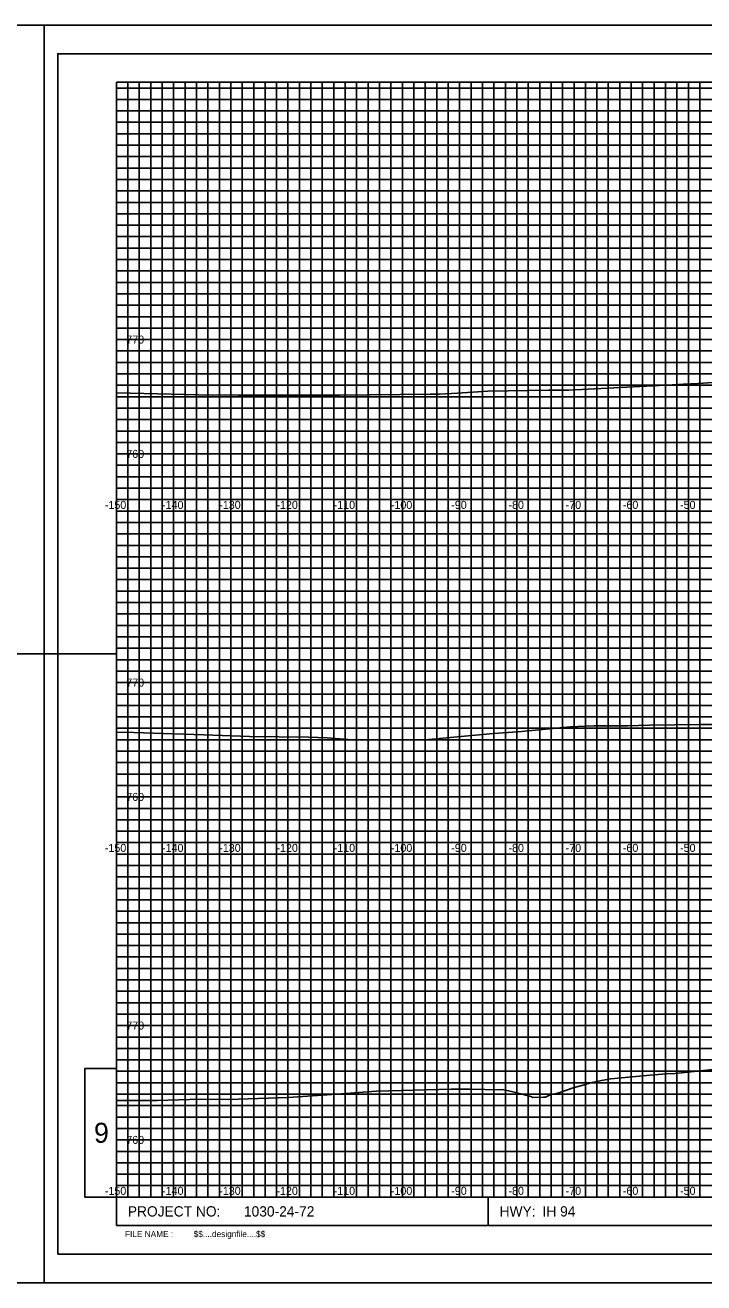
# Model space of a CAD drawing. Extents: x 578243 to 601557, y 174899 to 175559.
# Drawn here: x 601213.9 to 601332.5, y 175338.8 to 175558.8 of the extents above; entities that cross this region are included whole.
import ezdxf

# ---------------------------------------------------------------- set-up
doc = ezdxf.new("R2010")
doc.units = 0
for name, color, linetype in [('E_PROF_Grid', 7, 'Continuous'), ('E_PROF_GridMin', 7, 'Continuous'), ('P_E_XS_Ground', 7, 'Continuous'), ('P_XS_Text', 7, 'Continuous'), ('PLT_Sheet_Border', 7, 'Continuous'), ('PLT_Sheet_Info', 7, 'Continuous')]:
    doc.layers.add(name, color=color, linetype=linetype)

msp = doc.modelspace()

# ---------------------------------------------------------------- linework, layer by layer
at = {"layer": 'E_PROF_Grid'}
for p, q in [((601239.84, 175353.8), (601239.84, 175548.8)), ((601249.84, 175353.8), (601249.84, 175548.8)), ((601259.84, 175353.8), (601259.84, 175548.8)), ((601269.84, 175353.8), (601269.84, 175548.8)), ((601279.84, 175353.8), (601279.84, 175548.8)), ((601289.84, 175353.8), (601289.84, 175548.8)), ((601299.84, 175353.8), (601299.84, 175548.8)), ((601309.84, 175353.8), (601309.84, 175548.8)), ((601319.84, 175353.8), (601319.84, 175548.8)), ((601329.84, 175353.8), (601329.84, 175548.8)), ((601229.84, 175543.8), (601544.84, 175543.8)), ((601229.84, 175533.8), (601544.84, 175533.8)), ((601229.84, 175523.8), (601544.84, 175523.8)), ((601229.84, 175513.8), (601544.84, 175513.8)), ((601229.84, 175503.8), (601544.84, 175503.8)), ((601229.84, 175493.8), (601544.84, 175493.8)), ((601229.84, 175483.8), (601544.84, 175483.8)), ((601229.84, 175473.8), (601544.84, 175473.8)), ((601229.84, 175463.8), (601544.84, 175463.8)), ((601229.84, 175453.8), (601544.84, 175453.8)), ((601229.84, 175443.8), (601544.84, 175443.8)), ((601229.84, 175433.8), (601544.84, 175433.8)), ((601229.84, 175423.8), (601544.84, 175423.8)), ((601229.84, 175413.8), (601544.84, 175413.8)), ((601229.84, 175403.8), (601544.84, 175403.8)), ((601229.84, 175393.8), (601544.84, 175393.8)), ((601229.84, 175383.8), (601544.84, 175383.8)), ((601229.84, 175373.8), (601544.84, 175373.8)), ((601229.84, 175363.8), (601544.84, 175363.8))]:
    msp.add_line(p, q, dxfattribs=at)
at = {"layer": 'E_PROF_GridMin'}
for p, q in [((601229.84, 175547.8), (601544.84, 175547.8)), ((601231.84, 175353.8), (601231.84, 175548.8)), ((601233.84, 175353.8), (601233.84, 175548.8)), ((601235.84, 175353.8), (601235.84, 175548.8)), ((601237.84, 175353.8), (601237.84, 175548.8)), ((601241.84, 175353.8), (601241.84, 175548.8)), ((601243.84, 175353.8), (601243.84, 175548.8)), ((601245.84, 175353.8), (601245.84, 175548.8)), ((601247.84, 175353.8), (601247.84, 175548.8)), ((601251.84, 175353.8), (601251.84, 175548.8)), ((601253.84, 175353.8), (601253.84, 175548.8)), ((601255.84, 175353.8), (601255.84, 175548.8)), ((601257.84, 175353.8), (601257.84, 175548.8)), ((601261.84, 175353.8), (601261.84, 175548.8)), ((601263.84, 175353.8), (601263.84, 175548.8)), ((601265.84, 175353.8), (601265.84, 175548.8)), ((601267.84, 175353.8), (601267.84, 175548.8)), ((601271.84, 175353.8), (601271.84, 175548.8)), ((601273.84, 175353.8), (601273.84, 175548.8)), ((601275.84, 175353.8), (601275.84, 175548.8)), ((601277.84, 175353.8), (601277.84, 175548.8)), ((601281.84, 175353.8), (601281.84, 175548.8)), ((601283.84, 175353.8), (601283.84, 175548.8)), ((601285.84, 175353.8), (601285.84, 175548.8)), ((601287.84, 175353.8), (601287.84, 175548.8)), ((601291.84, 175353.8), (601291.84, 175548.8)), ((601293.84, 175353.8), (601293.84, 175548.8)), ((601295.84, 175353.8), (601295.84, 175548.8)), ((601297.84, 175353.8), (601297.84, 175548.8)), ((601301.84, 175353.8), (601301.84, 175548.8)), ((601303.84, 175353.8), (601303.84, 175548.8)), ((601305.84, 175353.8), (601305.84, 175548.8)), ((601307.84, 175353.8), (601307.84, 175548.8)), ((601311.84, 175353.8), (601311.84, 175548.8)), ((601313.84, 175353.8), (601313.84, 175548.8)), ((601315.84, 175353.8), (601315.84, 175548.8)), ((601317.84, 175353.8), (601317.84, 175548.8)), ((601321.84, 175353.8), (601321.84, 175548.8)), ((601323.84, 175353.8), (601323.84, 175548.8)), ((601325.84, 175353.8), (601325.84, 175548.8)), ((601327.84, 175353.8), (601327.84, 175548.8)), ((601331.84, 175353.8), (601331.84, 175548.8)), ((601229.84, 175545.8), (601544.84, 175545.8)), ((601229.84, 175541.8), (601544.84, 175541.8)), ((601229.84, 175539.8), (601544.84, 175539.8)), ((601229.84, 175537.8), (601544.84, 175537.8)), ((601229.84, 175535.8), (601544.84, 175535.8)), ((601229.84, 175531.8), (601544.84, 175531.8)), ((601229.84, 175529.8), (601544.84, 175529.8)), ((601229.84, 175527.8), (601544.84, 175527.8)), ((601229.84, 175525.8), (601544.84, 175525.8)), ((601229.84, 175521.8), (601544.84, 175521.8)), ((601229.84, 175519.8), (601544.84, 175519.8)), ((601229.84, 175517.8), (601544.84, 175517.8)), ((601229.84, 175515.8), (601544.84, 175515.8)), ((601229.84, 175511.8), (601544.84, 175511.8)), ((601229.84, 175509.8), (601544.84, 175509.8)), ((601229.84, 175507.8), (601544.84, 175507.8)), ((601229.84, 175505.8), (601544.84, 175505.8)), ((601229.84, 175501.8), (601544.84, 175501.8)), ((601229.84, 175499.8), (601544.84, 175499.8)), ((601229.84, 175497.8), (601544.84, 175497.8)), ((601229.84, 175495.8), (601544.84, 175495.8)), ((601229.84, 175491.8), (601544.84, 175491.8)), ((601229.84, 175489.8), (601544.84, 175489.8)), ((601229.84, 175487.8), (601544.84, 175487.8)), ((601229.84, 175485.8), (601544.84, 175485.8)), ((601229.84, 175481.8), (601544.84, 175481.8)), ((601229.84, 175479.8), (601544.84, 175479.8)), ((601229.84, 175477.8), (601544.84, 175477.8)), ((601229.84, 175475.8), (601544.84, 175475.8)), ((601229.84, 175471.8), (601544.84, 175471.8)), ((601229.84, 175469.8), (601544.84, 175469.8)), ((601229.84, 175467.8), (601544.84, 175467.8)), ((601229.84, 175465.8), (601544.84, 175465.8)), ((601229.84, 175461.8), (601544.84, 175461.8)), ((601229.84, 175459.8), (601544.84, 175459.8)), ((601229.84, 175457.8), (601544.84, 175457.8)), ((601229.84, 175455.8), (601544.84, 175455.8)), ((601229.84, 175451.8), (601544.84, 175451.8)), ((601229.84, 175449.8), (601544.84, 175449.8)), ((601229.84, 175447.8), (601544.84, 175447.8)), ((601229.84, 175445.8), (601544.84, 175445.8)), ((601229.84, 175441.8), (601544.84, 175441.8)), ((601229.84, 175439.8), (601544.84, 175439.8)), ((601229.84, 175437.8), (601544.84, 175437.8)), ((601229.84, 175435.8), (601544.84, 175435.8)), ((601229.84, 175431.8), (601544.84, 175431.8)), ((601229.84, 175429.8), (601544.84, 175429.8)), ((601229.84, 175427.8), (601544.84, 175427.8)), ((601229.84, 175425.8), (601544.84, 175425.8)), ((601229.84, 175421.8), (601544.84, 175421.8)), ((601229.84, 175419.8), (601544.84, 175419.8)), ((601229.84, 175417.8), (601544.84, 175417.8)), ((601229.84, 175415.8), (601544.84, 175415.8)), ((601229.84, 175411.8), (601544.84, 175411.8)), ((601229.84, 175409.8), (601544.84, 175409.8)), ((601229.84, 175407.8), (601544.84, 175407.8)), ((601229.84, 175405.8), (601544.84, 175405.8)), ((601229.84, 175401.8), (601544.84, 175401.8)), ((601229.84, 175399.8), (601544.84, 175399.8)), ((601229.84, 175397.8), (601544.84, 175397.8)), ((601229.84, 175395.8), (601544.84, 175395.8)), ((601229.84, 175391.8), (601544.84, 175391.8)), ((601229.84, 175389.8), (601544.84, 175389.8)), ((601229.84, 175387.8), (601544.84, 175387.8)), ((601229.84, 175385.8), (601544.84, 175385.8)), ((601229.84, 175381.8), (601544.84, 175381.8)), ((601229.84, 175379.8), (601544.84, 175379.8)), ((601229.84, 175377.8), (601544.84, 175377.8)), ((601229.84, 175375.8), (601544.84, 175375.8)), ((601229.84, 175371.8), (601544.84, 175371.8)), ((601229.84, 175369.8), (601544.84, 175369.8)), ((601229.84, 175367.8), (601544.84, 175367.8)), ((601229.84, 175365.8), (601544.84, 175365.8)), ((601229.84, 175361.8), (601544.84, 175361.8)), ((601229.84, 175359.8), (601544.84, 175359.8)), ((601229.84, 175357.8), (601544.84, 175357.8)), ((601229.84, 175355.8), (601544.84, 175355.8)), ((601217.19, 175338.8), (601217.19, 175348.8)), ((601207.19, 175338.8), (601217.19, 175338.8))]:
    msp.add_line(p, q, dxfattribs=at)
at = {"layer": 'P_E_XS_Ground'}
for points in [[(601229.84, 175494.48), (601246.61, 175494.09), (601248.9, 175494.11), (601251.11, 175494.05), (601268.9, 175494.05), (601284.71, 175494.27), (601286.35, 175494.23), (601289.45, 175494.45), (601294.75, 175494.76), (601305.41, 175494.94), (601308.07, 175494.95), (601308.91, 175494.97), (601328.12, 175495.94), (601328.91, 175495.97), (601331.57, 175496.14), (601338.37, 175496.56)], [(601229.84, 175435.12), (601232.85, 175435.04), (601245.13, 175434.63), (601253.13, 175434.36), (601263.44, 175434.27), (601266.66, 175434.11), (601270.34, 175433.87), (601275.98, 175433.81), (601278.64, 175433.8), (601283.46, 175433.8), (601283.74, 175433.79), (601285.06, 175433.91), (601295.75, 175434.91), (601300.02, 175435.2), (601309.24, 175436.03), (601313.29, 175436.25), (601319.18, 175436.25), (601323.02, 175436.34), (601327.46, 175436.39), (601331.89, 175436.47), (601334.67, 175436.49)], [(601229.84, 175370.7), (601236.95, 175370.72), (601244.56, 175370.92), (601249.37, 175370.87), (601259.89, 175371.24), (601268.35, 175371.83), (601275.33, 175372.33), (601288.38, 175372.68), (601289.05, 175372.69), (601289.44, 175372.66), (601291.58, 175372.66), (601296.99, 175372.58), (601297.35, 175372.59), (601299.13, 175372.2), (601300.56, 175371.88), (601300.77, 175371.78), (601302.29, 175371.41), (601302.66, 175371.23), (601304.5, 175371.26), (601304.84, 175371.29), (601305.68, 175371.66), (601306.8, 175371.93), (601307.36, 175372.08), (601309.68, 175372.91), (601310.96, 175373.25), (601311.63, 175373.45), (601312.71, 175373.76), (601314.67, 175374.21), (601316.26, 175374.51), (601323.18, 175375.14), (601325.96, 175375.33), (601327.52, 175375.42), (601331.98, 175375.89), (601335.74, 175376.27)]]:
    msp.add_lwpolyline(points, dxfattribs=at)
at = {"layer": 'PLT_Sheet_Border'}
for points in [[(600877.19, 175338.8), (601217.19, 175338.8), (601217.19, 175558.8), (600877.19, 175558.8)], [(601217.19, 175338.8), (601557.19, 175338.8), (601557.19, 175558.8), (601217.19, 175558.8)], [(601219.59, 175343.8), (601550.59, 175343.8), (601550.59, 175553.8), (601219.59, 175553.8)]]:
    msp.add_lwpolyline(points, close=True, dxfattribs=at)
at = {"layer": 'PLT_Sheet_Info'}
for p, q in [((601207.19, 175558.8), (601217.19, 175558.8)), ((601217.19, 175548.8), (601217.19, 175558.8)), ((601217.19, 175548.8), (601217.19, 175558.8)), ((601217.19, 175558.8), (601227.19, 175558.8)), ((601229.84, 175548.8), (601544.84, 175548.8)), ((601229.84, 175348.8), (601229.84, 175548.8)), ((601217.19, 175443.8), (601217.19, 175453.8)), ((601217.19, 175443.8), (601217.19, 175453.8)), ((601217.19, 175448.8), (601204.84, 175448.8)), ((601217.19, 175448.8), (601229.84, 175448.8)), ((601229.84, 175353.8), (601544.84, 175353.8)), ((601294.84, 175348.8), (601294.84, 175353.8)), ((601217.19, 175338.8), (601217.19, 175348.8)), ((601229.84, 175348.8), (601544.84, 175348.8)), ((601217.19, 175338.8), (601227.19, 175338.8))]:
    msp.add_line(p, q, dxfattribs=at)
msp.add_lwpolyline([(601229.84, 175376.3), (601224.34, 175376.3), (601224.34, 175353.8), (601229.84, 175353.8)], close=True, dxfattribs=at)

# ---------------------------------------------------------------- texts
at = {"layer": 'P_XS_Text'}
for s, p in [('770', (601231.57, 175503.1)), ('760', (601231.57, 175483.1)), ('-150', (601227.82, 175474.18)), ('-140', (601237.82, 175474.18)), ('-130', (601247.82, 175474.18)), ('-120', (601257.82, 175474.18)), ('-110', (601267.82, 175474.18)), ('-100', (601277.82, 175474.18)), ('-90', (601288.38, 175474.18)), ('-80', (601298.38, 175474.18)), ('-70', (601308.38, 175474.18)), ('-60', (601318.38, 175474.18)), ('-50', (601328.38, 175474.18)), ('770', (601231.57, 175443.1)), ('760', (601231.57, 175423.1)), ('-150', (601227.82, 175414.18)), ('-140', (601237.82, 175414.18)), ('-130', (601247.82, 175414.18)), ('-120', (601257.82, 175414.18)), ('-110', (601267.82, 175414.18)), ('-100', (601277.82, 175414.18)), ('-90', (601288.38, 175414.18)), ('-80', (601298.38, 175414.18)), ('-70', (601308.38, 175414.18)), ('-60', (601318.38, 175414.18)), ('-50', (601328.38, 175414.18)), ('770', (601231.57, 175383.1)), ('760', (601231.57, 175363.1)), ('-150', (601227.82, 175354.19)), ('-140', (601237.82, 175354.19)), ('-130', (601247.82, 175354.19)), ('-120', (601257.82, 175354.19)), ('-110', (601267.82, 175354.19)), ('-100', (601277.82, 175354.19)), ('-90', (601288.38, 175354.19)), ('-80', (601298.38, 175354.19)), ('-70', (601308.38, 175354.19)), ('-60', (601318.38, 175354.19)), ('-50', (601328.38, 175354.19))]:
    msp.add_text(s, height=1.4, rotation=360, dxfattribs=at).set_placement(p)
at = {"layer": 'PLT_Sheet_Info'}
for s, height, p in [('9', 3.5, (601225.92, 175363.3)), ('PROJECT NO:', 1.8, (601231.84, 175350.4)), ('1030-24-72             ', 1.8, (601252.14, 175350.4)), ('HWY:', 1.8, (601296.84, 175350.4)), ('IH 94               ', 1.8, (601304.34, 175350.4)), ('FILE NAME :', 1.08, (601231.34, 175346.8))]:
    msp.add_text(s, height=height, dxfattribs=at).set_placement(p)
msp.add_text('$$....designfile....$$', height=1.08, rotation=360, dxfattribs=at).set_placement((601243.34, 175346.8))

doc.saveas('drawing.dxf')
